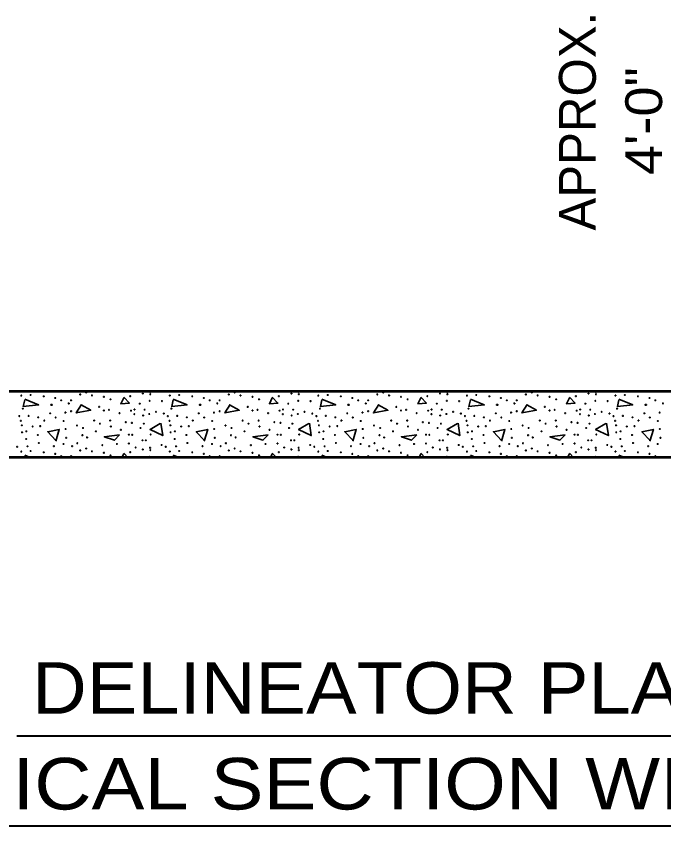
# Model space of a CAD drawing. Extents: x -54 to 626, y -41 to 399.
# Drawn here: x 34 to 78, y 80.9 to 135.9 of the extents above; entities that cross this region are included whole.
import ezdxf
from ezdxf.enums import TextEntityAlignment as Align

# ---------------------------------------------------------------- set-up
doc = ezdxf.new("R2010")
doc.units = 0
doc.header["$LTSCALE"] = 0.9
doc.layers.add('1', color=7, linetype='Continuous', lineweight=35)

msp = doc.modelspace()

# ---------------------------------------------------------------- linework, layer by layer
at = {"layer": '1', "lineweight": 53}
for p, q in [((9.1902, 110.4283), (80.6902, 110.4283)), ((80.6902, 105.9283), (9.1902, 105.9283))]:
    msp.add_line(p, q, dxfattribs=at)
at = {"layer": '1'}
for p, q in [((41.1882, 105.9283), (41.3128, 106.1778)), ((41.3128, 106.2177), (41.5877, 105.9283)), ((51.2682, 105.9283), (51.3928, 106.1778)), ((51.3928, 106.2177), (51.6677, 105.9283)), ((61.3482, 105.9283), (61.4728, 106.1778)), ((61.4728, 106.2177), (61.7477, 105.9283)), ((71.4282, 105.9283), (71.5528, 106.1778)), ((71.5528, 106.2177), (71.8277, 105.9283)), ((34.5691, 105.9283), (34.5928, 106.0378)), ((34.5928, 106.0777), (34.9624, 105.9283)), ((44.6491, 105.9283), (44.6728, 106.0378)), ((44.6728, 106.0777), (45.0424, 105.9283)), ((54.7291, 105.9283), (54.7528, 106.0378)), ((54.7528, 106.0777), (55.1224, 105.9283)), ((64.8091, 105.9283), (64.8328, 106.0378)), ((64.8328, 106.0777), (65.2024, 105.9283)), ((74.8891, 105.9283), (74.9128, 106.0378)), ((74.9128, 106.0777), (75.2824, 105.9283))]:
    msp.add_line(p, q, dxfattribs=at)
at = {"layer": '1', "lineweight": 40}
for p, q in [((34.0568, 87.0277), (102.1171, 87.0277)), ((23.3503, 80.9192), (113.7321, 80.9192))]:
    msp.add_line(p, q, dxfattribs=at)
at = {"layer": '1'}
for points in [[(41.3128, 110.0177), (41.6928, 109.6178), (41.1128, 109.5777), (41.3128, 109.9778)], [(51.3928, 110.0177), (51.7728, 109.6178), (51.1928, 109.5777), (51.3928, 109.9778)], [(61.4728, 110.0177), (61.8528, 109.6178), (61.2728, 109.5777), (61.4728, 109.9778)], [(71.5528, 110.0177), (71.9328, 109.6178), (71.3528, 109.5777), (71.5528, 109.9778)], [(34.5928, 109.8777), (35.5328, 109.4977), (34.4928, 109.3777), (34.5928, 109.8377)], [(38.4128, 109.4977), (39.0728, 109.1377), (38.0928, 108.9577), (38.4528, 109.5177)], [(44.6728, 109.8777), (45.6128, 109.4977), (44.5728, 109.3777), (44.6728, 109.8377)], [(48.4928, 109.4977), (49.1528, 109.1377), (48.1728, 108.9577), (48.5328, 109.5177)], [(54.7528, 109.8777), (55.6928, 109.4977), (54.6528, 109.3777), (54.7528, 109.8377)], [(58.5728, 109.4977), (59.2328, 109.1377), (58.2528, 108.9577), (58.6128, 109.5177)], [(64.8328, 109.8777), (65.7728, 109.4977), (64.7328, 109.3777), (64.8328, 109.8377)], [(68.6528, 109.4977), (69.3128, 109.1377), (68.3328, 108.9577), (68.6928, 109.5177)], [(74.9128, 109.8777), (75.8528, 109.4977), (74.8128, 109.3777), (74.9128, 109.8377)], [(36.6928, 107.0378), (36.9328, 107.8377), (36.1528, 107.6778), (36.7128, 107.0777)], [(43.7928, 108.2377), (43.0928, 107.8377), (43.9528, 107.4177), (43.8328, 108.2578)], [(46.7728, 107.0378), (47.0128, 107.8377), (46.2328, 107.6778), (46.7928, 107.0777)], [(53.8728, 108.2377), (53.1728, 107.8377), (54.0328, 107.4177), (53.9128, 108.2578)], [(56.8528, 107.0378), (57.0928, 107.8377), (56.3128, 107.6778), (56.8728, 107.0777)], [(63.9528, 108.2377), (63.2528, 107.8377), (64.1128, 107.4177), (63.9928, 108.2578)], [(66.9328, 107.0378), (67.1728, 107.8377), (66.3928, 107.6778), (66.9528, 107.0777)], [(74.0328, 108.2377), (73.3328, 107.8377), (74.1928, 107.4177), (74.0728, 108.2578)], [(77.0128, 107.0378), (77.2528, 107.8377), (76.4728, 107.6778), (77.0328, 107.0777)]]:
    msp.add_lwpolyline(points, dxfattribs=at)
for points in [[(41.0328, 107.4577), (39.9928, 107.3377), (40.6728, 107.0977)], [(51.1128, 107.4577), (50.0728, 107.3377), (50.7528, 107.0977)], [(61.1928, 107.4577), (60.1528, 107.3377), (60.8328, 107.0977)], [(71.2728, 107.4577), (70.2328, 107.3377), (70.9128, 107.0977)]]:
    msp.add_lwpolyline(points, close=True, dxfattribs=at)
for centre in [(34.3587, 110.128), (34.9948, 110.1678), (35.8828, 110.0749), (36.6647, 109.9689), (38.3611, 110.2075), (38.7587, 110.3353), (39.1563, 110.1412), (39.9647, 110.0484), (41.7539, 110.0882), (42.1194, 110.4016), (42.6098, 110.2738), (43.1001, 110.3883), (43.1133, 110.2208), (44.4387, 110.128), (45.0748, 110.1678), (45.9628, 110.0749), (46.7447, 109.9689), (48.4411, 110.2075), (48.8387, 110.3353), (49.2363, 110.1412), (50.0447, 110.0484), (51.8339, 110.0882), (52.1994, 110.4016), (52.6898, 110.2738), (53.1801, 110.3883), (53.1933, 110.2208), (54.5187, 110.128), (55.1548, 110.1678), (56.0428, 110.0749), (56.8247, 109.9689), (58.5211, 110.2075), (58.9187, 110.3353), (59.3163, 110.1412), (60.1247, 110.0484), (61.9139, 110.0882), (62.2794, 110.4016), (62.7698, 110.2738), (63.2601, 110.3883), (63.2733, 110.2208), (64.5987, 110.128), (65.2348, 110.1678), (66.1228, 110.0749), (66.9047, 109.9689), (68.6011, 110.2075), (68.9987, 110.3353), (69.3963, 110.1412), (70.2047, 110.0484), (71.9939, 110.0882), (72.3594, 110.4016), (72.8498, 110.2738), (73.3401, 110.3883), (73.3533, 110.2208), (74.6787, 110.128), (75.3148, 110.1678), (76.2028, 110.0749), (76.9847, 109.9689), (36.3864, 109.5049), (36.4394, 109.5049), (37.0623, 109.8098), (37.5792, 109.5977), (37.7383, 109.8098), (40.4154, 109.8761), (42.3977, 109.5845), (43.0736, 109.77), (43.9086, 109.7568), (46.4664, 109.5049), (46.5194, 109.5049), (47.1423, 109.8098), (47.6592, 109.5977), (47.8183, 109.8098), (50.4954, 109.8761), (52.4777, 109.5845), (53.1536, 109.77), (53.9886, 109.7568), (56.5464, 109.5049), (56.5994, 109.5049), (57.2223, 109.8098), (57.7392, 109.5977), (57.8983, 109.8098), (60.5754, 109.8761), (62.5577, 109.5845), (63.2336, 109.77), (64.0686, 109.7568), (66.6264, 109.5049), (66.6794, 109.5049), (67.3023, 109.8098), (67.8192, 109.5977), (67.9783, 109.8098), (70.6554, 109.8761), (72.6377, 109.5845), (73.3136, 109.77), (74.1486, 109.7568), (76.7064, 109.5049), (76.7594, 109.5049), (77.3823, 109.8098), (77.8992, 109.5977), (34.4647, 109.2397), (36.3201, 108.9215), (37.3539, 108.9746), (37.7382, 109.0674), (39.6467, 109.3591), (39.9647, 109.1205), (40.3093, 109.1602), (41.025, 108.9348), (41.8069, 109.1072), (42.0266, 108.8685), (42.0398, 109.1867), (42.729, 109.1735), (43.0471, 108.8818), (43.4977, 109.0276), (44.0279, 108.9083), (44.5447, 109.2397), (46.4001, 108.9215), (47.4339, 108.9746), (47.8182, 109.0674), (49.7267, 109.3591), (50.0447, 109.1205), (50.3893, 109.1602), (51.105, 108.9348), (51.8869, 109.1072), (52.1066, 108.8685), (52.1198, 109.1867), (52.809, 109.1735), (53.1271, 108.8818), (53.5777, 109.0276), (54.1079, 108.9083), (54.6247, 109.2397), (56.4801, 108.9215), (57.5139, 108.9746), (57.8982, 109.0674), (59.8067, 109.3591), (60.1247, 109.1205), (60.4693, 109.1602), (61.185, 108.9348), (61.9669, 109.1072), (62.1866, 108.8685), (62.1998, 109.1867), (62.889, 109.1735), (63.2071, 108.8818), (63.6577, 109.0276), (64.1879, 108.9083), (64.7047, 109.2397), (66.5601, 108.9215), (67.5939, 108.9746), (67.9782, 109.0674), (69.8867, 109.3591), (70.2047, 109.1205), (70.5493, 109.1602), (71.265, 108.9348), (72.0469, 109.1072), (72.2666, 108.8685), (72.2798, 109.1867), (72.969, 109.1735), (73.2871, 108.8818), (73.7377, 109.0276), (74.2679, 108.9083), (74.7847, 109.2397), (76.6401, 108.9215), (77.6739, 108.9746), (34.2261, 108.736), (34.3322, 108.4178), (34.8623, 108.7493), (35.5117, 108.6564), (35.9225, 108.4311), (36.6912, 108.6432), (37.2346, 108.4045), (39.3021, 108.4311), (40.3889, 108.4311), (41.4491, 108.325), (41.8675, 108.272), (42.623, 108.7757), (44.3061, 108.736), (44.4122, 108.4178), (44.9423, 108.7493), (45.5917, 108.6564), (46.0025, 108.4311), (46.7712, 108.6432), (47.3146, 108.4045), (49.3821, 108.4311), (50.4689, 108.4311), (51.5291, 108.325), (51.9475, 108.272), (52.703, 108.7757), (54.3861, 108.736), (54.4922, 108.4178), (55.0223, 108.7493), (55.6717, 108.6564), (56.0825, 108.4311), (56.8512, 108.6432), (57.3946, 108.4045), (59.4621, 108.4311), (60.5489, 108.4311), (61.6091, 108.325), (62.0275, 108.272), (62.783, 108.7757), (64.4661, 108.736), (64.5722, 108.4178), (65.1023, 108.7493), (65.7517, 108.6564), (66.1625, 108.4311), (66.9312, 108.6432), (67.4746, 108.4045), (69.5421, 108.4311), (70.6289, 108.4311), (71.6891, 108.325), (72.1075, 108.272), (72.863, 108.7757), (74.5461, 108.736), (74.6522, 108.4178), (75.1823, 108.7493), (75.8317, 108.6564), (76.2425, 108.4311), (77.0112, 108.6432), (77.5546, 108.4045), (34.3984, 108.1129), (35.1274, 108.0333), (35.6442, 108.0599), (37.3672, 107.861), (38.1358, 108.0996), (38.5467, 107.9272), (39.6997, 108.219), (40.4418, 108.0333), (41.1178, 107.808), (42.4507, 107.9272), (42.676, 108.219), (44.4784, 108.1129), (45.2074, 108.0333), (45.7242, 108.0599), (47.4472, 107.861), (48.2158, 108.0996), (48.6267, 107.9272), (49.7797, 108.219), (50.5218, 108.0333), (51.1978, 107.808), (52.5307, 107.9272), (52.756, 108.219), (54.5584, 108.1129), (55.2874, 108.0333), (55.8042, 108.0599), (57.5272, 107.861), (58.2958, 108.0996), (58.7067, 107.9272), (59.8597, 108.219), (60.6018, 108.0333), (61.2778, 107.808), (62.6107, 107.9272), (62.836, 108.219), (64.6384, 108.1129), (65.3674, 108.0333), (65.8842, 108.0599), (67.6072, 107.861), (68.3758, 108.0996), (68.7867, 107.9272), (69.9397, 108.219), (70.6818, 108.0333), (71.3578, 107.808), (72.6907, 107.9272), (72.916, 108.219), (74.7184, 108.1129), (75.4474, 108.0333), (75.9642, 108.0599), (77.6872, 107.861), (34.4117, 107.6356), (34.69, 107.1848), (34.7033, 107.7019), (35.4852, 107.45), (37.4069, 107.2644), (38.5069, 107.4368), (38.825, 107.2909), (39.4214, 107.7019), (41.6612, 107.4766), (41.8873, 107.461), (43.1399, 107.4898), (44.4917, 107.6356), (44.77, 107.1848), (44.7833, 107.7019), (45.5652, 107.45), (47.4869, 107.2644), (48.5869, 107.4368), (48.905, 107.2909), (49.5014, 107.7019), (51.7412, 107.4766), (51.9673, 107.461), (53.2199, 107.4898), (54.5717, 107.6356), (54.85, 107.1848), (54.8633, 107.7019), (55.6452, 107.45), (57.5669, 107.2644), (58.6669, 107.4368), (58.985, 107.2909), (59.5814, 107.7019), (61.8212, 107.4766), (62.0473, 107.461), (63.2999, 107.4898), (64.6517, 107.6356), (64.93, 107.1848), (64.9433, 107.7019), (65.7252, 107.45), (67.6469, 107.2644), (68.7469, 107.4368), (69.065, 107.2909), (69.6614, 107.7019), (71.9012, 107.4766), (72.1273, 107.461), (73.3799, 107.4898), (74.7317, 107.6356), (75.01, 107.1848), (75.0233, 107.7019), (75.8052, 107.45), (77.7269, 107.2644), (34.0803, 106.6546), (34.7827, 106.6811), (35.5514, 106.9065), (36.5719, 106.6943), (37.2213, 106.8402), (37.8045, 106.6943), (38.1623, 106.8932), (39.8587, 106.7606), (40.8527, 106.8402), (41.6612, 106.8799), (42.5832, 107.092), (42.8085, 107.092), (43.882, 106.7738), (44.1603, 106.6546), (44.8627, 106.6811), (45.6314, 106.9065), (46.6519, 106.6943), (47.3013, 106.8402), (47.8845, 106.6943), (48.2423, 106.8932), (49.9387, 106.7606), (50.9327, 106.8402), (51.7412, 106.8799), (52.6632, 107.092), (52.8885, 107.092), (53.962, 106.7738), (54.2403, 106.6546), (54.9427, 106.6811), (55.7114, 106.9065), (56.7319, 106.6943), (57.3813, 106.8402), (57.9645, 106.6943), (58.3223, 106.8932), (60.0187, 106.7606), (61.0127, 106.8402), (61.8212, 106.8799), (62.7432, 107.092), (62.9685, 107.092), (64.042, 106.7738), (64.3203, 106.6546), (65.0227, 106.6811), (65.7914, 106.9065), (66.8119, 106.6943), (67.4613, 106.8402), (68.0445, 106.6943), (68.4023, 106.8932), (70.0987, 106.7606), (71.0927, 106.8402), (71.9012, 106.8799), (72.8232, 107.092), (73.0485, 107.092), (74.122, 106.7738), (74.4003, 106.6546), (75.1027, 106.6811), (75.8714, 106.9065), (76.8919, 106.6943), (77.5413, 106.8402), (34.3587, 106.328), (34.9948, 106.3678), (35.8828, 106.2749), (36.6647, 106.1689), (38.3611, 106.4075), (38.7587, 106.5353), (39.1563, 106.3412), (39.9647, 106.2484), (40.4154, 106.0761), (41.7539, 106.2882), (42.1194, 106.6016), (42.6098, 106.4738), (43.1001, 106.5883), (43.1133, 106.4208), (44.4387, 106.328), (45.0748, 106.3678), (45.9628, 106.2749), (46.7447, 106.1689), (48.4411, 106.4075), (48.8387, 106.5353), (49.2363, 106.3412), (50.0447, 106.2484), (50.4954, 106.0761), (51.8339, 106.2882), (52.1994, 106.6016), (52.6898, 106.4738), (53.1801, 106.5883), (53.1933, 106.4208), (54.5187, 106.328), (55.1548, 106.3678), (56.0428, 106.2749), (56.8247, 106.1689), (58.5211, 106.4075), (58.9187, 106.5353), (59.3163, 106.3412), (60.1247, 106.2484), (60.5754, 106.0761), (61.9139, 106.2882), (62.2794, 106.6016), (62.7698, 106.4738), (63.2601, 106.5883), (63.2733, 106.4208), (64.5987, 106.328), (65.2348, 106.3678), (66.1228, 106.2749), (66.9047, 106.1689), (68.6011, 106.4075), (68.9987, 106.5353), (69.3963, 106.3412), (70.2047, 106.2484), (70.6554, 106.0761), (71.9939, 106.2882), (72.3594, 106.6016), (72.8498, 106.4738), (73.3401, 106.5883), (73.3533, 106.4208), (74.6787, 106.328), (75.3148, 106.3678), (76.2028, 106.2749), (76.9847, 106.1689), (37.0623, 106.0098), (37.7383, 106.0098), (43.0736, 105.97), (43.9086, 105.9568), (47.1423, 106.0098), (47.8183, 106.0098), (53.1536, 105.97), (53.9886, 105.9568), (57.2223, 106.0098), (57.8983, 106.0098), (63.2336, 105.97), (64.0686, 105.9568), (67.3023, 106.0098), (67.9783, 106.0098), (73.3136, 105.97), (74.1486, 105.9568), (77.3823, 106.0098)]:
    msp.add_circle(centre, 0.0265, dxfattribs=at)
for centre in [(34.0803, 110.4546), (44.1603, 110.4546), (54.2403, 110.4546), (64.3203, 110.4546), (74.4003, 110.4546)]:
    msp.add_arc(centre, 0.0265, 262.28656, 277.71344, dxfattribs=at)

# ---------------------------------------------------------------- texts
msp.add_text('APPROX.', height=2.5, rotation=90, dxfattribs=at).set_placement((73.3417, 128.7625), align=Align.CENTER)
at = {"layer": '1', "width": 1.1}
msp.add_text('4\'-0"', height=2.5, rotation=90, dxfattribs=at).set_placement((77.8417, 128.7626), align=Align.CENTER)
at = {"layer": '1'}
for s, width, p in [('DELINEATOR PLACEMENT', 1.1, (67.982, 88.5277)), ('TYPICAL SECTION WITH CURBING', 1.15, (67.982, 82.0277))]:
    msp.add_text(s, height=3.5, dxfattribs=dict(at, width=width)).set_placement(p, align=Align.CENTER)

doc.saveas('drawing.dxf')
